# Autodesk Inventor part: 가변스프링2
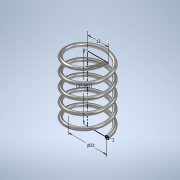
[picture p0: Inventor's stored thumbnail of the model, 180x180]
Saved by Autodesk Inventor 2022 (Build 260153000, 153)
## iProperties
Created: 2021-07
Part Number: 가변스프링2
Material: 강철, 연강
Document SubType Name: Modeling
Designer: micke
Density: 7.85 g/cm^3
Appearance: 반연마
Mass: 8.42401 g
Surface Area: 21.7265 cm^2
Volume: 1.07312 cm^3
Author: micke
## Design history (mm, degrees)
sketch "스케치1"
  geometry: L1 (0, 0)-(0, 37.261); L2 (0, 37.261)-(12, 37.261); L3 (0, 0)-(11, 0); C1 r 1 at (11, 0)
  constraints: 6 end point, 2 horizontal, 1 centre point, 1 coincident, 1 vertical
  dimensions: "d0" = 37.2612 distance of L1.start L1.end (derived); "d1" = 2 diameter of C1; "d2" = 22 diameter of L3.end L1; "d3" = 12 distance of L1.end L2.end
feature "코일1" sketch "스케치1" pitch "d4" = 10; turns "d6" = 5; dims "d5" = 37.2612 (= d0), "d7" = 0, angle "d8" = 90 deg, angle "d9" = 90 deg, "d10" = 0, "d11" = 0
sketch "스케치2"
  geometry: L1 (37.261, 12.5)-(0, 12.5); L2 (0, 12.5)-(0, -12.5); L3 (0, -12.5)-(37.261, -12.5); L4 (37.261, -12.5)-(37.261, 12.5); 2 further points
  constraints: 8 end point, 2 parallel, 1 coincident, 1 horizontal, 1 midpoint, 1 perpendicular
  dimensions: "d12" = 37.2612 distance of L1.start L1.end (= d0); "d13" = 25 distance of L3.end L1.start
extrude "돌출1" sketch "스케치2" extent not by distance; stored distance "d14" = 0; taper "d15" = 0 deg
node "솔리드1"
feature "A9D066F2-1C7D-4E18-AEED-F7BC21143FA4" dims "d4" = 10, "d5" = 37.2612 (= d0), "d6" = 50, "d7" = 0, "d8" = 90 deg, "d9" = 90 deg, "d10" = 0, "d11" = 0
